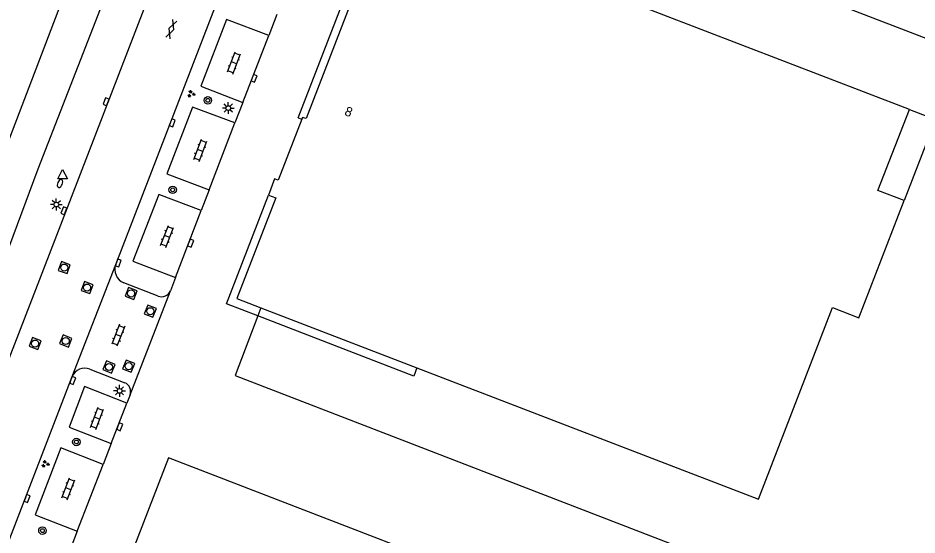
# Model space of a CAD drawing. Extents: x 131000 to 133013, y 393000 to 396501.
# Drawn here: x 131317.4 to 131413.1, y 393730.5 to 393785.7 of the extents above; entities that cross this region are included whole.
import ezdxf

# ---------------------------------------------------------------- set-up
doc = ezdxf.new("R2010")
doc.units = 0
for name, color, linetype in [('gg-afsc-hekwerk', 7, 'Continuous'), ('gg-anno-huisnummerreeks BGT', 7, 'Continuous'), ('gg-bbg-hoofdgebouw', 7, 'Continuous'), ('gg-bbg-onder overbouw', 7, 'Continuous'), ('gg-bbg-pand overbouw', 7, 'Continuous'), ('gg-knt-verharding', 7, 'Continuous'), ('gg-kntw-bovenkant insteek waterloop', 7, 'Continuous'), ('gg-kntw-waterlijn', 7, 'Continuous'), ('gt-symb-boom', 7, 'Continuous'), ('gt-symb-brandkraan', 7, 'Continuous'), ('gt-symb-gesloten verharding', 7, 'Continuous'), ('gt-symb-groenvak', 7, 'Continuous'), ('gt-symb-klinker verharding', 7, 'Continuous'), ('gt-symb-kolk', 7, 'Continuous'), ('gt-symb-lichtmast', 7, 'Continuous'), ('gt-symb-rioolschacht', 7, 'Continuous'), ('gt-symb-waterafsluiter', 7, 'Continuous')]:
    doc.layers.add(name, color=color, linetype=linetype)

# ---------------------------------------------------------------- blocks, each defined once
blk = doc.blocks.new('gt0-LMAST')
at = {"layer": 'gt-symb-lichtmast'}
for p, q in [((-0.182, 0.173), (-0.447, 0.438)), ((-0.005, 0.246), (-0.005, 0.621)), ((0.172, 0.173), (0.437, 0.438)), ((-0.255, -0.004), (-0.63, -0.004)), ((-0.182, -0.181), (-0.447, -0.446)), ((-0.005, -0.254), (-0.005, -0.629)), ((0.437, -0.446), (0.172, -0.181)), ((0.245, -0.004), (0.62, -0.004))]:
    blk.add_line(p, q, dxfattribs=at)
blk.add_circle((-0.005, -0.004), 0.25, dxfattribs=at)
blk = doc.blocks.new('gt0-KOLK')
at = {"layer": 'gt-symb-kolk'}
blk.add_lwpolyline([(0, 0), (0.375, 0), (0.375, 0.4), (-0.375, 0.4), (-0.375, 0), (0, 0)], dxfattribs=at)
blk = doc.blocks.new('gt0-RS')
at = {"layer": 'gt-symb-rioolschacht'}
blk.add_lwpolyline([(-0.5, -0.5), (0.5, -0.5), (0.5, 0.5), (-0.5, 0.5)], close=True, dxfattribs=at)
blk.add_circle((0, 0), 0.375, dxfattribs=at)
blk = doc.blocks.new('gt0-KL1')
at = {"layer": 'gt-symb-klinker verharding'}
for p, q in [((-1.15, 0.3), (1.15, 0.3)), ((-1, -0.3), (-1, 0.3)), ((-0.5, 0.3), (-0.5, 0.45)), ((0, -0.3), (0, 0.3)), ((0.5, 0.3), (0.5, 0.45)), ((1, -0.3), (1, 0.3)), ((-1.15, -0.3), (1.15, -0.3)), ((-0.5, -0.45), (-0.5, -0.3)), ((0.5, -0.45), (0.5, -0.3))]:
    blk.add_line(p, q, dxfattribs=at)
blk = doc.blocks.new('gt0-BR')
at = {"layer": 'gt-symb-brandkraan'}
for centre, radius, start, end in [((-0.244, 0), 0.206, 107.56694, 252.43307), ((0.599, -2.664), 3, 106.89205, 107.56694), ((0, -0.691), 0.938, 73.10799, 106.89205), ((-0.599, -2.664), 3, 72.43309, 73.10799), ((0.244, 0), 0.206, 287.56695, 72.43309), ((0.599, 2.664), 3, 252.43307, 253.10797), ((0, 0.691), 0.938, 253.10797, 286.89206), ((-0.599, 2.664), 3, 286.89206, 287.56695)]:
    blk.add_arc(centre, radius, start, end, dxfattribs=at)
blk = doc.blocks.new('gt0-WAFSL')
at = {"layer": 'gt-symb-waterafsluiter'}
for p, q in [((-0.5, -0.333), (0, 0.667)), ((0, 0.667), (0.5, -0.333)), ((0.5, -0.333), (-0.5, -0.333))]:
    blk.add_line(p, q, dxfattribs=at)
blk = doc.blocks.new('gt0-BOOM')
at = {"layer": 'gt-symb-boom'}
for radius in [0.4, 0.2]:
    blk.add_circle((0, 0), radius, dxfattribs=at)
blk = doc.blocks.new('gt0-GRVAK')
at = {"layer": 'gt-symb-groenvak'}
for p, q in [((-0.11, 0.189), (-0.228, 0.24)), ((-0.182, 0.153), (0.088, 0.153)), ((-0.091, 0.211), (-0.156, 0.322)), ((-0.047, 0.214), (-0.047, 0.393)), ((-0.004, 0.211), (0.061, 0.322)), ((0.015, 0.189), (0.133, 0.24)), ((0.262, -0.052), (0.197, 0.059)), ((0.305, -0.049), (0.305, 0.13)), ((0.349, -0.052), (0.414, 0.059)), ((-0.245, -0.228), (-0.363, -0.177)), ((-0.318, -0.264), (-0.047, -0.264)), ((-0.226, -0.206), (-0.291, -0.095)), ((-0.183, -0.203), (-0.183, -0.024)), ((-0.139, -0.206), (-0.074, -0.095)), ((-0.12, -0.228), (-0.002, -0.177)), ((0.243, -0.074), (0.125, -0.023)), ((0.17, -0.11), (0.441, -0.11)), ((0.368, -0.074), (0.486, -0.023))]:
    blk.add_line(p, q, dxfattribs=at)
blk = doc.blocks.new('gt0-GESVH1')
at = {"layer": 'gt-symb-gesloten verharding'}
for p, q in [((-0.992, -0.261), (0.008, 0.239)), ((0.008, -0.261), (-0.992, 0.239)), ((0.008, 0.239), (1.008, -0.261)), ((1.008, 0.239), (0.008, -0.261))]:
    blk.add_line(p, q, dxfattribs=at)

msp = doc.modelspace()

# ---------------------------------------------------------------- linework, layer by layer
at = {"layer": 'gg-afsc-hekwerk'}
msp.add_line((131343.26, 393754.753), (131342.936, 393753.9), dxfattribs=at)
msp.add_lwpolyline([(131342.936, 393753.9), (131340.514, 393747.536), (131414.167, 393719.091), (131435.814, 393775.11), (131380.171, 393796.563)], dxfattribs=at)
at = {"layer": 'gg-bbg-hoofdgebouw'}
msp.add_line((131412.312, 393775.907), (131375.896, 393789.928), dxfattribs=at)
for points in [[(131347.62, 393774.859), (131345.096, 393768.368), (131344.713, 393768.525), (131344.048, 393766.781)], [(131359.872, 393748.357), (131396.245, 393734.354), (131404.102, 393754.793), (131406.914, 393753.703), (131411.735, 393766.206)], [(131379.232, 393721.081), (131333.418, 393738.758), (131325.263, 393717.626)]]:
    msp.add_lwpolyline(points, dxfattribs=at)
at = {"layer": 'gg-bbg-onder overbouw'}
msp.add_line((131343.26, 393754.753), (131359.872, 393748.357), dxfattribs=at)
for points in [[(131359.292, 393796.321), (131356.704, 393797.317), (131348.058, 393774.955), (131347.697, 393775.056), (131347.62, 393774.859)], [(131411.735, 393766.206), (131408.954, 393767.278), (131412.312, 393775.907)], [(131344.048, 393766.781), (131344.842, 393766.478), (131340.68, 393755.746), (131343.26, 393754.753)]]:
    msp.add_lwpolyline(points, dxfattribs=at)
at = {"layer": 'gg-bbg-pand overbouw'}
msp.add_line((131347.215, 393775.016), (131347.62, 393774.859), dxfattribs=at)
for points in [[(131347.215, 393775.016), (131356.275, 393798.466), (131359.632, 393797.173)], [(131412.312, 393775.907), (131415.087, 393774.853), (131411.735, 393766.206)], [(131342.936, 393753.9), (131339.573, 393755.198), (131344.048, 393766.781)], [(131359.872, 393748.357), (131359.538, 393747.493), (131342.936, 393753.9)]]:
    msp.add_lwpolyline(points, dxfattribs=at)
at = {"layer": 'gg-knt-verharding'}
for p, q in [((131327.794, 393759.391), (131344.696, 393803.254)), ((131344.943, 393786.034), (131344.085, 393783.81)), ((131341.331, 393776.664), (131344.085, 393783.81)), ((131341.331, 393776.664), (131340.471, 393774.472)), ((131337.739, 393767.332), (131340.471, 393774.472)), ((131337.739, 393767.332), (131336.882, 393765.128)), ((131334.156, 393757.991), (131336.882, 393765.128)), ((131323.156, 393747.458), (131327.794, 393759.391)), ((131332.303, 393756.023), (131328.65, 393757.43)), ((131334.156, 393757.991), (131333.622, 393756.583)), ((131329.321, 393745.479), (131333.622, 393756.583)), ((131325.025, 393748.226), (131328.773, 393746.781)), ((131313.066, 393721.237), (131323.156, 393747.458)), ((131327.301, 393740.289), (131328.989, 393744.611)), ((131329.321, 393745.479), (131328.989, 393744.611)), ((131327.301, 393740.289), (131326.454, 393738.047)), ((131323.699, 393730.953), (131326.454, 393738.047)), ((131323.699, 393730.953), (131322.835, 393728.708))]:
    msp.add_line(p, q, dxfattribs=at)
for points in [[(131355.727, 393851.362), (131321.3, 393762.023), (131311.652, 393737.11), (131296.688, 393698.315)], [(131344.085, 393783.81), (131339.592, 393785.499), (131336.842, 393778.386), (131341.331, 393776.664)], [(131340.471, 393774.472), (131335.973, 393776.16), (131333.239, 393769.064), (131337.739, 393767.332)], [(131336.882, 393765.128), (131332.397, 393766.841), (131329.627, 393759.728), (131334.156, 393757.991)], [(131328.989, 393744.611), (131324.478, 393746.394), (131322.82, 393742.026), (131327.301, 393740.289)], [(131326.454, 393738.047), (131321.96, 393739.823), (131319.223, 393732.698), (131323.699, 393730.953)]]:
    msp.add_lwpolyline(points, dxfattribs=at)
for centre, radius, start, end in [((131329.234, 393758.852), 1.538, 159.49924, 247.66445), ((131332.68, 393756.968), 1.017, 248.23091, 337.77775), ((131324.497, 393746.854), 1.47, 68.93948, 155.7375), ((131328.353, 393745.838), 1.032, 339.63996, 66.01161)]:
    msp.add_arc(centre, radius, start, end, dxfattribs=at)
at = {"layer": 'gg-kntw-bovenkant insteek waterloop'}
msp.add_lwpolyline([(131375.352, 393914.857), (131358.065, 393868.418), (131348.765, 393844.959), (131339.126, 393819.96), (131329.317, 393794.86), (131319.505, 393769.527), (131310.311, 393744.867), (131300.831, 393720.659), (131296.153, 393708.202)], dxfattribs=at)
at = {"layer": 'gg-kntw-waterlijn'}
msp.add_lwpolyline([(131292.541, 393709.577), (131297.286, 393722.588), (131303.63, 393739.007), (131311.889, 393760.873), (131326.539, 393799.18), (131343.777, 393843.128), (131358.673, 393881.667), (131368.196, 393905.416)], dxfattribs=at)

# ---------------------------------------------------------------- block references
at = {"layer": 'gt-symb-boom'}
for p in [(131337.599, 393776.88), (131333.857, 393767.337), (131323.602, 393740.462), (131319.991, 393731.015)]:
    msp.add_blockref('gt0-BOOM', p, dxfattribs=at)
at = {"layer": 'gt-symb-brandkraan', "rotation": -113.69497103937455}
msp.add_blockref('gt0-BR', (131321.866, 393768.01), dxfattribs=at)
at = {"layer": 'gt-symb-gesloten verharding', "rotation": -110.84426442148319}
msp.add_blockref('gt0-GESVH1', (131333.725, 393784.473), dxfattribs=at)
at = {"layer": 'gt-symb-groenvak'}
for p in [(131335.82, 393777.567), (131320.3, 393738.121)]:
    msp.add_blockref('gt0-GRVAK', p, dxfattribs=at)
at = {"layer": 'gt-symb-klinker verharding'}
for p, rotation in [((131340.385, 393780.868), 68.9007877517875), ((131336.796, 393771.548), 68.90078774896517), ((131333.262, 393762.37), 68.90078775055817), ((131328.06, 393751.851), -111.09921224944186), ((131325.798, 393742.987), 68.90078775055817), ((131322.745, 393735.465), 68.90078774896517)]:
    msp.add_blockref('gt0-KL1', p, dxfattribs=dict(at, rotation=rotation))
at = {"layer": 'gt-symb-kolk'}
for p, rotation in [((131342.335, 393779.294), -110.91820498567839), ((131326.956, 393776.662), 68.84735479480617), ((131333.625, 393774.55), -111.04574081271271), ((131322.463, 393765.042), 68.90078775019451), ((131335.587, 393761.721), -110.97171056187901), ((131327.869, 393759.606), -109.2143118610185), ((131323.028, 393747.096), -111.09921224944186), ((131328.036, 393742.163), -111.40773994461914), ((131318.174, 393734.519), -111.04574081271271)]:
    msp.add_blockref('gt0-KOLK', p, dxfattribs=dict(at, rotation=rotation))
at = {"layer": 'gt-symb-lichtmast'}
for p in [(131339.786, 393776.063), (131321.475, 393765.779), (131328.202, 393745.918)]:
    msp.add_blockref('gt0-LMAST', p, dxfattribs=at)
at = {"layer": 'gt-symb-rioolschacht'}
for p, rotation in [((131322.313, 393759.055), -109.39552832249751), ((131324.749, 393756.924), -110.24750151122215), ((131329.436, 393756.292), -21.71629047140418), ((131331.476, 393754.401), 158.0497154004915), ((131319.212, 393750.954), 68.71983368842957), ((131322.475, 393751.223), -112.15258650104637), ((131327.078, 393748.456), 157.79435666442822), ((131329.175, 393748.543), 158.028289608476)]:
    msp.add_blockref('gt0-RS', p, dxfattribs=dict(at, rotation=rotation))
at = {"layer": 'gt-symb-waterafsluiter'}
msp.add_blockref('gt0-WAFSL', (131322.142, 393768.829), dxfattribs=at)

# ---------------------------------------------------------------- texts
at = {"layer": 'gg-anno-huisnummerreeks BGT'}
msp.add_text('8', height=1, rotation=338.8, dxfattribs=at).set_placement((131352.077, 393775.335))

doc.saveas('drawing.dxf')
